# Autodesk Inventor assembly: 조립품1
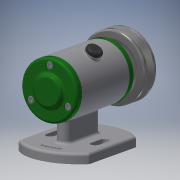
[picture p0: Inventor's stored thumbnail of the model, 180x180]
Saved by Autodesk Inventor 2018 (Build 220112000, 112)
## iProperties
Created: 2022-02
Part Number: 조립품1
Document SubType Name: Assembly
Designer: 1class 2
Author: 1class 2
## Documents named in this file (14)
- C:\Users\1class 2\Desktop\720206V1027\조립품1.iam
- C:\Users\1class 2\Desktop\720206V1027\본체.ipt
- C:\Users\1class 2\Desktop\720206V1027\축.ipt
- C:\Users\1class 2\Desktop\720206V1027\베어링 6002.ipt
- C:\Users\1class 2\Desktop\720206V1027\뒤커버.ipt
- C:\Users\1class 2\Desktop\720206V1027\앞커버.ipt
- C:\Users\1class 2\Desktop\720206V1027\오일 실 15 x 25 x 7.ipt
- C:\Users\1class 2\Desktop\720206V1027\키 3 x 3 x 12.ipt
- C:\Users\1class 2\Desktop\720206V1027\V벨트풀리.ipt
- C:\Users\1class 2\Desktop\720206V1027\평와셔 8 x 17.ipt
- C:\Users\1class 2\Desktop\720206V1027\스프링와셔 8.ipt
- C:\Users\1class 2\Desktop\720206V1027\너트 M8.ipt
- C:\Users\1class 2\Desktop\720206V1027\고무 캡.ipt
- C:\Users\1class 2\Desktop\720206V1027\볼트 M4 x 10.ipt
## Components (2 placed, 2 different names)
1. V벨트풀리:1
2. 고무 캡:1
